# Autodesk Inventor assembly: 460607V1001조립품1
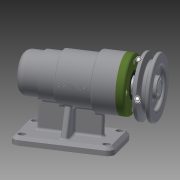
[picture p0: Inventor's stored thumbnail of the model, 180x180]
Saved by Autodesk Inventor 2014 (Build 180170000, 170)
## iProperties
Created: 2016-06
Part Number: 460607V1001조립품1
Document SubType Name: Assembly
Designer: SEC
Author: SEC
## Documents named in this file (12)
- C:\Documents and Settings\SEC\바탕 화면\460607V1001\460607V1001조립품1.iam
- C:\Documents and Settings\SEC\바탕 화면\460607V1001\460607V1001본체.ipt
- C:\Documents and Settings\SEC\바탕 화면\460607V1001\축.ipt
- C:\Documents and Settings\SEC\바탕 화면\460607V1001\베어링 51202.ipt
- C:\Documents and Settings\SEC\바탕 화면\460607V1001\어댑터슬리브.ipt
- C:\Documents and Settings\SEC\바탕 화면\460607V1001\베어링 6004.ipt
- C:\Documents and Settings\SEC\바탕 화면\460607V1001\볼트 M4 x 12.ipt
- C:\Documents and Settings\SEC\바탕 화면\460607V1001\커버.ipt
- C:\Documents and Settings\SEC\바탕 화면\460607V1001\오일 실.ipt
- C:\Documents and Settings\SEC\바탕 화면\460607V1001\키 5 x 5 x 16.ipt
- C:\Documents and Settings\SEC\바탕 화면\460607V1001\V벨트풀리.ipt
- C:\Documents and Settings\SEC\바탕 화면\460607V1001\멈춤나사 M3x8.ipt
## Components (7 placed, 3 different names)
1. 460607V1001본체:1
2. ISO 4762 M4 x 12:1
3. V벨트풀리:1 — 각도:1
4. ISO 4762 M4 x 12:2
5. ISO 4762 M4 x 12:3
6. ISO 4762 M4 x 12:4
7. ISO 4762 M4 x 12:5
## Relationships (1: Angle 1)
- 각도:1 [Angle]: V벨트풀리:1
